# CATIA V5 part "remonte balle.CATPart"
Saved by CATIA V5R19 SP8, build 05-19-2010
Part number: remonte balle
Bounding box of the stored display mesh (mm): x -28 to 0, y 0 to 16.25, z 0 to 14.39
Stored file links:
  E:\Catia parts\GLOCK\remonte balle.CATPart
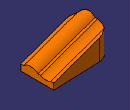
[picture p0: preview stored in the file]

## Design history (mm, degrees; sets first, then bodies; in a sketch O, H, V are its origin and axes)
Body1 (main body)
  Solid1: solid without history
